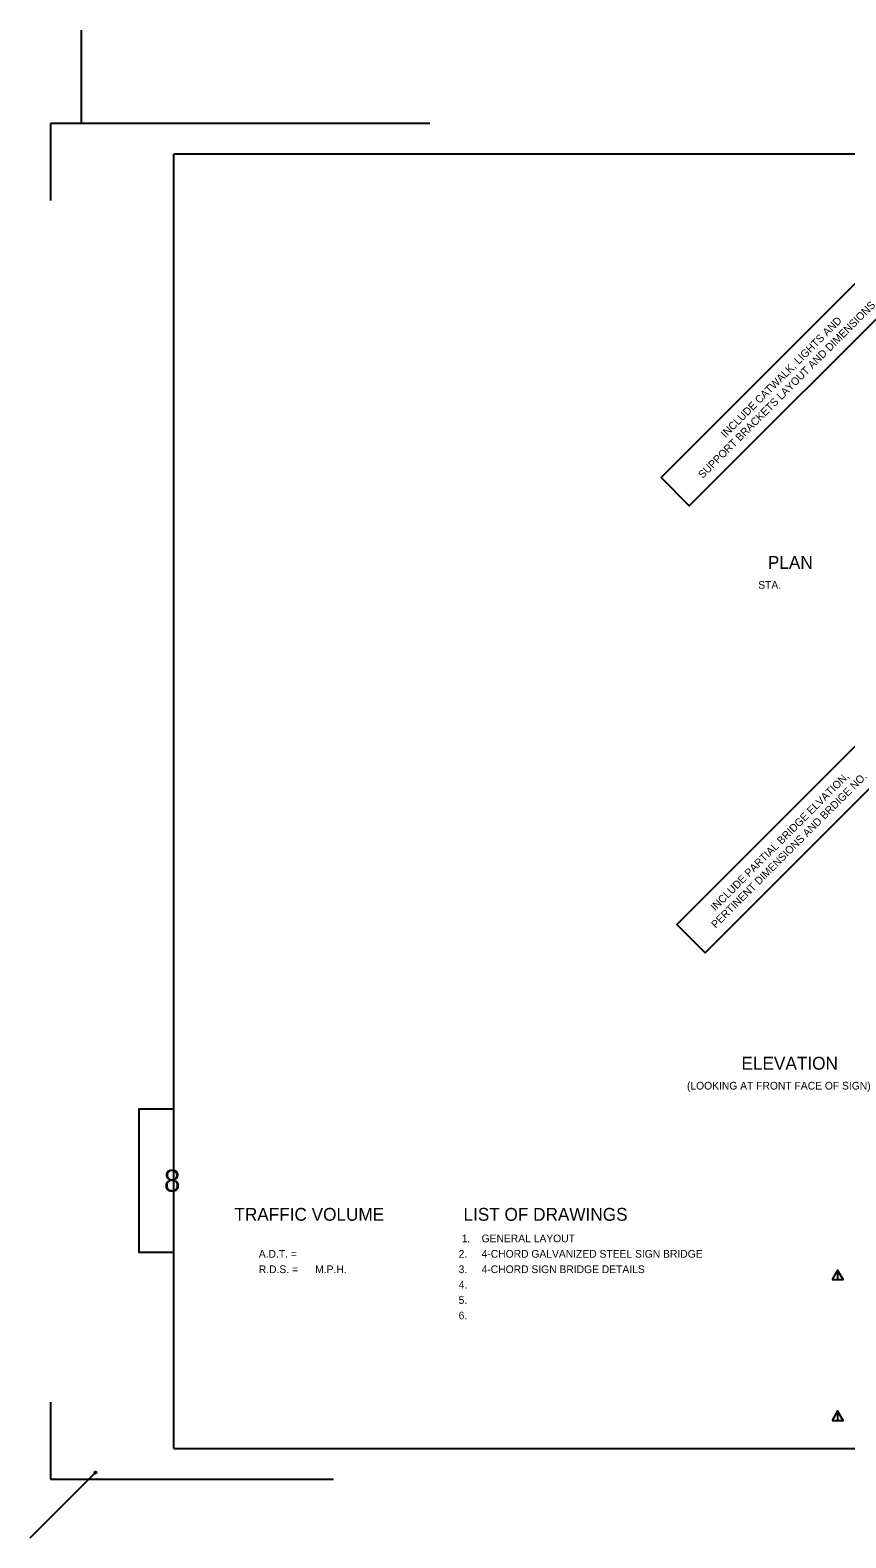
# Model space of a CAD drawing. Extents: x -21 to 58.5, y -16 to 40.8.
# Drawn here: x -21 to 8.7, y -14.3 to 40.8 of the extents above; entities that cross this region are included whole.
import ezdxf

# ---------------------------------------------------------------- set-up
doc = ezdxf.new("R2010")
doc.units = 0
for name, color, linetype in [('Level 1', 7, 'Continuous'), ('Level 11', 7, 'Continuous'), ('Level 13', 7, 'Continuous'), ('Level 2', 7, 'Continuous'), ('Level 49', 7, 'Continuous')]:
    doc.layers.add(name, color=color, linetype=linetype)

msp = doc.modelspace()

# ---------------------------------------------------------------- linework, layer by layer
at = {"layer": 'Level 1'}
for p, q in [((-6.452, 37.351), (-20.291, 37.351)), ((-20.291, 37.351), (-20.291, 34.533)), ((-15.791, -11.023), (-15.791, 36.226)), ((54.804, 36.226), (-15.791, 36.226)), ((-20.291, -9.33), (-20.291, -12.148)), ((-15.791, -11.023), (54.804, -11.023)), ((-20.291, -12.148), (-9.968, -12.148))]:
    msp.add_line(p, q, dxfattribs=at)
msp.add_lwpolyline([(-15.791, 1.363), (-17.068, 1.363), (-17.068, -3.86), (-15.791, -3.86)], close=True, dxfattribs=at)
at = {"layer": 'Level 11'}
msp.add_lwpolyline([(1.993, 24.418), (10.347, 32.772), (11.379, 31.74), (3.025, 23.386)], close=True, dxfattribs=at)
at = {"layer": 'Level 13'}
msp.add_lwpolyline([(2.576, 8.101), (9.707, 15.232), (10.739, 14.2), (3.608, 7.069)], close=True, dxfattribs=at)
at = {"layer": 'Level 2'}
for p, q in [((-19.166, 37.351), (-19.166, 40.753)), ((-21.039, -14.289), (-18.652, -11.902))]:
    msp.add_line(p, q, dxfattribs=at)
for points in [[(8.239, -4.862), (8.64, -4.862), (8.439, -4.515)], [(8.439, -4.515), (8.439, -4.862), (8.64, -4.862)], [(8.239, -10.001), (8.64, -10.001), (8.439, -9.654)], [(8.439, -9.654), (8.439, -10.001), (8.64, -10.001)]]:
    msp.add_lwpolyline(points, close=True, dxfattribs=at)
at = {"layer": 'Level 49'}
msp.add_circle((-18.653, -11.902), 0.0342, dxfattribs=at)

# ---------------------------------------------------------------- texts
at = {"layer": 'Level 1'}
for s, height, p in [('PLAN', 0.4694, (5.894, 21.086)), ('ELEVATION', 0.4694, (4.93, 2.803)), ('8', 0.812, (-16.157, -1.655)), ('TRAFFIC VOLUME', 0.46874, (-13.582, -2.713)), ('LIST OF DRAWINGS', 0.46874, (-5.218, -2.713))]:
    msp.add_text(s, height=height, dxfattribs=at).set_placement(p)
at = {"layer": 'Level 11'}
for s, p in [('SUPPORT BRACKETS LAYOUT AND DIMENSIONS', (3.518, 24.367)), ('INCLUDE CATWALK, LIGHTS AND', (4.349, 25.855))]:
    msp.add_text(s, height=0.28125, rotation=45, dxfattribs=at).set_placement(p)
for s, p in [(' 5.  ', (-5.5, -5.749)), (' 6.  ', (-5.5, -6.311))]:
    msp.add_text(s, height=0.2813, dxfattribs=at).set_placement(p)
at = {"layer": 'Level 13'}
for s, p in [('INCLUDE PARTIAL BRIDGE ELVATION,', (3.972, 8.579)), ('PERTINENT DIMENSIONS AND BRDIGE NO.', (3.992, 7.943))]:
    msp.add_text(s, height=0.28125, rotation=45, dxfattribs=at).set_placement(p)
at = {"layer": 'Level 2'}
for s, height, p in [('STA.           ', 0.28125, (5.543, 20.361)), ('(LOOKING AT FRONT FACE OF SIGN)', 0.28125, (2.94, 2.077)), (' 1.  ', 0.2813, (-5.384, -3.499)), ('GENERAL LAYOUT', 0.28125, (-4.556, -3.499)), ('A.D.T. =           ', 0.28125, (-12.691, -4.061)), (' 2.  ', 0.2813, (-5.5, -4.061)), ('4-CHORD GALVANIZED STEEL SIGN BRIDGE', 0.28125, (-4.556, -4.061)), ('R.D.S. =      M.P.H.', 0.28125, (-12.691, -4.624)), (' 3.  ', 0.2813, (-5.5, -4.624)), ('4-CHORD SIGN BRIDGE DETAILS', 0.28125, (-4.556, -4.624)), (' 4.  ', 0.2813, (-5.5, -5.186))]:
    msp.add_text(s, height=height, dxfattribs=at).set_placement(p)

doc.saveas('drawing.dxf')
